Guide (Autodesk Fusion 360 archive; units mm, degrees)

design "Guide" references "Base"
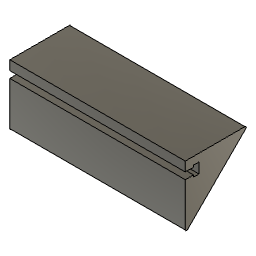
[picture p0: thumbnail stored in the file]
parameter "width" = 140
parameter "extra_padding" = 0
component_insert "Component Insert"
sketch "Sketch2" plane through (40, 0, 0) normal (1, 0, 0) x axis (0, 1, 0)
  line L1 (44.7318, 45.6759) -> (44.7318, 48.9559)
  line L2 (48.9918, 45.6759) -> (44.7318, 45.6759)
  line L3 (48.9918, 47.1259) -> (48.9918, 45.6759)
  line L4 (55.6118, 47.1259) -> (48.9918, 47.1259)
  line L5 (55.6118, 52.4859) -> (55.6118, 47.1259)
  line L6 (48.9918, 52.4859) -> (55.6118, 52.4859)
  line L7 (48.9918, 53.9359) -> (48.9918, 52.4859)
  line L8 (44.7318, 53.9359) -> (48.9918, 53.9359)
  line L9 (44.7318, 50.6559) -> (44.7318, 53.9359)
  line L10 (44.7318, 48.9559) -> (44.7318, 50.6559)
  line L11 (28.6118, 54.0559) -> (28.6118, 50.6559)
  line L12 (33.1118, 54.0559) -> (28.6118, 54.0559)
  line L13 (33.1118, 52.6059) -> (33.1118, 54.0559)
  line L14 (39.6118, 52.6059) -> (33.1118, 52.6059)
  line L15 (39.6118, 60) -> (39.6118, 52.6059)
  line L16 (19.6118, 60) -> (39.6118, 60)
  line L17 (19.6118, 23.2332) -> (19.6118, 60)
  line L18 (39.6118, 39.6118) -> (22.1725, 22.1725)
  line L19 (39.6118, 47.0059) -> (39.6118, 39.6118)
  line L20 (33.1118, 47.0059) -> (39.6118, 47.0059)
  line L21 (33.1118, 45.5559) -> (33.1118, 47.0059)
  line L22 (28.6118, 45.5559) -> (33.1118, 45.5559)
  line L23 (28.6118, 48.9559) -> (28.6118, 45.5559)
  arc A1 centre (44.7318, 49.8059) radius 0.85 clockwise from (44.7318, 50.6559) to (44.7318, 48.9559)
  arc A2 centre (44.7318, 49.8059) radius 0.85 clockwise from (44.7318, 50.6559) to (44.7318, 48.9559)
  arc A3 centre (28.6118, 49.8059) radius 0.85 clockwise from (28.6118, 48.9559) to (28.6118, 50.6559)
  arc A4 centre (21.1118, 23.2332) radius 1.5 clockwise from (22.1725, 22.1725) to (19.6118, 23.2332)
  point P14 (44.7318, 50.6559)
  point P16 (44.7318, 50.6559)
  point P2 (44.7318, 48.9559)
  point P17 (44.7318, 48.9559)
  coincident P14 P16
  coincident P2 P17
sketch "Sketch4" plane through (40, 50.1718, 49.8059) normal (1, 0, 0) x axis (0, 1, 0)
  line L1 (-5.44, -0.85) -> (-5.44, 0.85)
  line L2 (-5.44, 10.1941) -> (-5.44, 0)
  line L3 (-5.44, -39.8059) -> (-5.44, 10.1941)
  line L4 (75.5574, 41.1915) -> (-5.44, -39.8059)
  line L5 (109.1076, -39.8059) -> (-5.44, -39.8059)
  line L6 (86, 10.1941) -> (-5.44, 10.1941)
  point P5 (-5.44, 0)
  point P6 (-5.44, 10.1941)
  point P7 (-5.44, -39.8059)
  midpoint L1 P5
  horizontal L5
  perpendicular L2 L6
  dimension "d9" distance P6 P7 = 50
  dimension "d11" angle L4 L5 = 45
extrude "Extrude3" new body sketch "Sketch4" profile of L1 L3 L4 L6 along normal blind 140 (= "width")
extrude "Extrude4" cut sketch "Sketch2" profile of A1 L1 L2 L3 L4 L5 L6 L7 L8 L9 A2 L10 along normal blind 140 (= "width")
sketch "Filename" plane through (0, 0, 60) normal (0, 0, 1) x axis (1, 0, 0)
  dimension "d17" = 3
sketch "Fill wrong hole" plane through (180, 0, 0) normal (1, 0, 0) x axis (0, 1, 0)
  line L1 (48.9918, 53.9359) -> (44.7318, 53.9359)
  line L2 (48.9918, 52.4859) -> (48.9918, 53.9359)
  line L3 (55.6118, 52.4859) -> (48.9918, 52.4859)
  line L4 (55.6118, 47.1259) -> (55.6118, 52.4859)
  line L5 (48.9918, 47.1259) -> (55.6118, 47.1259)
  line L6 (48.9918, 45.6759) -> (48.9918, 47.1259)
  line L7 (44.7318, 45.6759) -> (48.9918, 45.6759)
  line L8 (44.7318, 10) -> (44.7318, 45.6759)
  line L9 (94.7318, 60) -> (44.7318, 10)
  line L10 (44.7318, 60) -> (94.7318, 60)
  line L11 (44.7318, 53.9359) -> (44.7318, 60)
  line L12 (44.7318, 45.6759) -> (44.7318, 53.9359)
  point P2 (44.7318, 53.9359)
  point P13 (44.7318, 53.9359)
  point P9 (44.7318, 45.6759)
  point P14 (44.7318, 45.6759)
  coincident P2 P13
  coincident P9 P14
extrude "Extrude5" add sketch "Fill wrong hole" profile of L1 L2 L3 L4 L5 L6 L7 L12 to an object
sketch "Sketch10" plane through (180, 0, 0) normal (1, 0, 0) x axis (0, 1, 0)
  line L1 (48.9918, 53.9359) -> (44.7318, 53.9359)
  line L2 (44.7318, 45.6759) -> (44.7318, 53.9359)
  line L3 (44.7318, 45.6759) -> (48.9918, 45.6759)
  line L4 (48.9918, 45.6759) -> (48.9918, 47.1259)
  line L5 (48.9918, 47.1259) -> (55.6118, 47.1259)
  line L6 (55.6118, 47.1259) -> (55.6118, 52.4859)
  line L7 (55.6118, 52.4859) -> (48.9918, 52.4859)
  line L8 (48.9918, 52.4859) -> (48.9918, 53.9359)
  line L9 (62.2318, 53.9359) -> (66.4918, 53.9359)
  line L10 (62.2318, 52.4859) -> (62.2318, 53.9359)
  line L11 (55.6118, 52.4859) -> (62.2318, 52.4859)
  line L12 (55.6118, 47.1259) -> (55.6118, 52.4859)
  line L13 (62.2318, 47.1259) -> (55.6118, 47.1259)
  line L14 (62.2318, 45.6759) -> (62.2318, 47.1259)
  line L15 (66.4918, 45.6759) -> (62.2318, 45.6759)
  line L16 (66.4918, 45.6759) -> (66.4918, 53.9359)
  point P2 (44.7318, 53.9359)
  point P12 (66.4918, 53.9359)
  point P3 (48.9918, 53.9359)
  point P13 (62.2318, 53.9359)
  point P4 (44.7318, 53.9359)
  point P20 (66.4918, 53.9359)
  point P5 (44.7318, 45.6759)
  point P21 (66.4918, 45.6759)
  point P6 (48.9918, 45.6759)
  point P18 (62.2318, 45.6759)
  point P7 (44.7318, 45.6759)
  point P19 (66.4918, 45.6759)
  point P8 (48.9918, 47.1259)
  point P17 (62.2318, 47.1259)
  point P9 (55.6118, 47.1259)
  point P16 (55.6118, 47.1259)
  point P10 (55.6118, 52.4859)
  point P15 (55.6118, 52.4859)
  point P11 (48.9918, 52.4859)
  point P14 (62.2318, 52.4859)
  symmetric P2 L6 P12
  symmetric P3 L6 P13
  symmetric P4 L6 P20
  symmetric P5 L6 P21
  symmetric P6 L6 P18
  symmetric P7 L6 P19
  symmetric P8 L6 P17
  symmetric P9 L6 P16
  symmetric P10 L6 P15
  symmetric L6 P11 P14
sketch "Sketch12" plane through (180, 0, 0) normal (1, 0, 0) x axis (0, 1, 0)
  line L1 (62.2318, 53.9359) -> (66.4918, 53.9359)
  line L2 (62.2318, 52.4859) -> (62.2318, 53.9359)
  line L3 (55.6118, 47.1259) -> (55.6118, 52.4859)
  line L4 (62.2318, 47.1259) -> (55.6118, 47.1259)
  line L5 (62.2318, 45.6759) -> (62.2318, 47.1259)
  line L6 (66.4918, 45.6759) -> (62.2318, 45.6759)
  line L7 (55.6118, 52.4859) -> (62.2318, 52.4859)
  line L8 (66.4918, 45.6759) -> (66.4918, 53.9359)
  line L9 (51.3518, 53.9359) -> (55.6118, 53.9359)
  line L10 (51.3518, 52.4859) -> (51.3518, 53.9359)
  line L11 (44.7318, 52.4859) -> (51.3518, 52.4859)
  line L12 (44.7318, 47.1259) -> (44.7318, 52.4859)
  line L13 (51.3518, 47.1259) -> (44.7318, 47.1259)
  line L14 (51.3518, 45.6759) -> (51.3518, 47.1259)
  line L15 (55.6118, 45.6759) -> (51.3518, 45.6759)
  line L16 (55.6118, 45.6759) -> (55.6118, 53.9359)
  dimension "d22" R-Pattern1-uDistance = -10.88
  dimension "d23" R-Pattern1-vDistance = 0
extrude "Extrude6" cut sketch "Sketch12" profile of L3 L9 L10 L11 L12 L13 L14 L15 L16 to an object
extrude "Extrude8" add of existing geometry blind 0 (= "extra_padding")
sketch "Sketch13" plane through (0, 0, 61) normal (0, 0, 1) x axis (-1, 0, 0)
  dimension "d33" = 3
sketch "Sketch15" plane through (0, 17.3659, -17.3659) normal (0, 0.7071, -0.7071) x axis (-1, 0, 0)
  dimension "d36" = 3
extrude "Extrude10" cut sketch "Sketch15" against normal blind 2
fillet "Fillet1" radius 1
extrude "Extrude9" cut sketch "Sketch13" against normal blind 2
sketch "Sketch14" plane through (0, 0, 60) normal (0, 0, 1) x axis (-1, 0, 0)
  line L1 (-40, -92.3176) -> (-180, -92.3176)
  line L2 (-40, -44.7318) -> (-40, -92.3176)
  line L3 (-180, -44.7318) -> (-40, -44.7318)
  line L4 (-180, -92.3176) -> (-180, -44.7318)

design "Base"
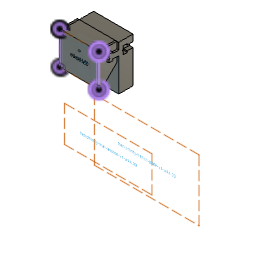
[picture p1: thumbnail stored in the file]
parameter "wall_anchor_height" = 60
parameter "wall_anchor_width" = 20
parameter "wall_anchor_angle" = 45
parameter "width_per_slot" = 40
parameter "slot_inner_width" = 8.5
parameter "slot_inner_height" = 4.5
parameter "slot_outer_width" = 5.6
parameter "slot_outer_height" = 6.5
parameter "slot_dept" = 15
parameter "print_tolerance" = 0.12
parameter "base_plate_thickness" = 16
parameter "base_plate_slot_height" = 50
parameter "wall_anchor_angle_rounded_border" = 1.5
parameter "base_plate_screw_hole_diameter" = 4
parameter "base_plate_screw_head_diameter" = 8
parameter "base_plate_screw_head_height" = 4
parameter "base_plate_screw_hole_side_distance" = 7
parameter "slot_screw_head_width" = 4.42 (= "4.3 mm + print_tolerance")
parameter "slot_screw_thread_width" = 2.12 (= "2 mm + print_tolerance")
parameter "slot_screw_head_height" = 2.12 (= "2 mm + print_tolerance")
parameter "width" = 44
parameter "filament_hole_width" = 1.7
sketch "Side" plane through (0, 0, 0) normal (1, 0, 0) x axis (0, 1, 0)
  line L1 (39.6118, 0) -> (19.6118, 0)
  line L2 (39.6118, 60) -> (39.6118, 0)
  line L3 (19.6118, 60) -> (39.6118, 60)
  line L4 (19.6118, 0) -> (19.6118, 60)
  line L5 (39.6118, 39.6118) -> (0, 0)
  line L6 (56.0196, 0) -> (0, 0)
  point P1 (0, 0)
  point P6 (0, 0)
  point P7 (39.6118, 39.6118)
  point P2 (19.6118, 0)
  point P3 (39.6118, 0)
  point P5 (19.6118, 60)
  horizontal L1
  vertical L2
  horizontal L3
  vertical L4
  horizontal L6
  coincident P1 P6
  coincident L2 P7
  dimension "d4" distance P2 P3 = 20 (= "wall_anchor_width")
  dimension "d5" distance P2 P5 = 60 (= "wall_anchor_height")
  dimension "d6" angle L5 L6 = 45 (= "wall_anchor_angle")
extrude "Extrude1" new body sketch "Side" profile of L1 L2 L3 L4 L5 along normal blind 40 (= "width_per_slot")
sketch "Slot LeftToRight" plane through (0, 0, 0) normal (-1, 0, 0) x axis (0, -1, 0)
  line L1 (-19.6118, 60) -> (-19.6118, 19.6118)
  line L2 (-39.6118, 60) -> (-19.6118, 60)
  line L3 (-39.6118, 39.6118) -> (-39.6118, 60)
  line L4 (-19.6118, 19.6118) -> (-39.6118, 39.6118)
  line L5 (-39.6118, 52.6059) -> (-39.6118, 49.8059)
  line L6 (-39.6118, 47.0059) -> (-39.6118, 49.8059)
  line L7 (-33.1118, 52.6059) -> (-39.6118, 52.6059)
  line L8 (-28.6118, 49.8059) -> (-39.6118, 49.8059)
  line L9 (-28.6118, 54.0559) -> (-28.6118, 49.8059)
  line L10 (-33.1118, 54.0559) -> (-28.6118, 54.0559)
  line L11 (-33.1118, 52.6059) -> (-33.1118, 54.0559)
  line L12 (-28.6118, 45.5559) -> (-28.6118, 49.8059)
  line L13 (-33.1118, 45.5559) -> (-28.6118, 45.5559)
  line L14 (-33.1118, 47.0059) -> (-33.1118, 45.5559)
  line L15 (-33.1118, 47.0059) -> (-39.6118, 47.0059)
  point P6 (-39.6118, 49.8059)
  point P7 (-39.6118, 52.6059)
  point P17 (-39.6118, 47.0059)
  point P9 (-33.1118, 52.6059)
  point P16 (-33.1118, 47.0059)
  point P10 (-28.6118, 49.8059)
  point P13 (-28.6118, 49.8059)
  point P11 (-28.6118, 54.0559)
  point P14 (-28.6118, 45.5559)
  point P12 (-33.1118, 54.0559)
  point P15 (-33.1118, 45.5559)
  midpoint L3 P6
  parallel L3 L5
  parallel L3 L6
  perpendicular L3 L7
  perpendicular L6 L8
  perpendicular L8 L9
  perpendicular L9 L10
  symmetric P7 L8 P17
  symmetric P9 L8 P16
  symmetric P10 L8 P13
  symmetric L8 P11 P14
  symmetric L8 P12 P15
  dimension "d80" distance P6 P7 = 2.8 (= "slot_outer_width / 2")
  dimension "d82" distance P7 P9 = 6.5 (= "slot_outer_height")
  dimension "d84" distance P6 P10 = 11 (= "slot_outer_height + slot_inner_height")
  dimension "d85" distance P10 P11 = 4.25 (= "slot_inner_width / 2")
  dimension "d86" distance P11 P12 = 4.5 (= "slot_inner_height")
extrude "Extrude3" cut sketch "Slot LeftToRight" profile of L3 L5 L6 L7 L9 L10 L11 L12 L13 L14 L15 against normal blind 40 (magnitude of "width_per_slot * -1")
sketch "Plate" plane through (0, 39.6118, 0) normal (0, 1, 0) x axis (-1, 0, 0)
  line L1 (0, 39.6118) -> (-40, 39.6118)
  line L2 (-40, 60) -> (0, 60)
  line L3 (0, 10) -> (0, 60)
  line L4 (-40, 10) -> (-40, 60)
  line L5 (-40, 10) -> (0, 10)
  line L6 (-40, 47.0059) -> (0, 47.0059)
  line L7 (-40, 52.6059) -> (-40, 60)
  line L8 (0, 60) -> (0, 52.6059)
  line L9 (0, 52.6059) -> (-40, 52.6059)
  line L10 (-40, 60) -> (0, 60)
  line L11 (-40, 39.6118) -> (-40, 47.0059)
  line L12 (0, 47.0059) -> (0, 39.6118)
  point P2 (0, 60)
  point P3 (-40, 60)
  point P4 (0, 10)
  point P5 (-40, 10)
  perpendicular L1 L3
  perpendicular L1 L4
  dimension "d36" distance P2 P3 = 40 (= "width_per_slot")
  dimension "d37" distance P2 P4 = 50 (= "base_plate_slot_height")
  dimension "d39" distance P3 P5 = 50 (= "base_plate_slot_height")
extrude "Extrude6" new body sketch "Plate" profile of L1 L2 L3 L4 L5 L6 L7 L8 L9 L10 along normal blind 16 (= "base_plate_thickness") bodies "Base plate with slot"
sketch "Slot" plane through (0, 0, 0) normal (-1, 0, 0) x axis (0, -1, 0)
  line L1 (-19.6118, 60) -> (-19.6118, 19.6118)
  line L2 (-39.6118, 60) -> (-19.6118, 60)
  line L3 (-39.6118, 52.6059) -> (-39.6118, 60)
  line L4 (-33.1118, 52.6059) -> (-39.6118, 52.6059)
  line L5 (-33.1118, 54.0559) -> (-33.1118, 52.6059)
  line L6 (-28.6118, 54.0559) -> (-33.1118, 54.0559)
  line L7 (-28.6118, 45.5559) -> (-28.6118, 54.0559)
  line L8 (-33.1118, 45.5559) -> (-28.6118, 45.5559)
  line L9 (-33.1118, 47.0059) -> (-33.1118, 45.5559)
  line L10 (-39.6118, 47.0059) -> (-33.1118, 47.0059)
  line L11 (-39.6118, 39.6118) -> (-39.6118, 47.0059)
  line L12 (-19.6118, 19.6118) -> (-39.6118, 39.6118)
  line L13 (-33.1118, 52.6059) -> (-39.6118, 52.6059)
  line L14 (-33.1118, 54.0559) -> (-33.1118, 52.6059)
  line L15 (-28.6118, 54.0559) -> (-33.1118, 54.0559)
  line L16 (-28.6118, 45.5559) -> (-28.6118, 54.0559)
  line L17 (-33.1118, 45.5559) -> (-28.6118, 45.5559)
  line L18 (-33.1118, 47.0059) -> (-33.1118, 45.5559)
  line L19 (-39.6118, 47.0059) -> (-33.1118, 47.0059)
  line L20 (-39.6118, 10) -> (-39.6118, 60)
  line L21 (-32.9918, 52.4859) -> (-39.6118, 52.4859)
  line L22 (-32.9918, 53.9359) -> (-32.9918, 52.4859)
  line L23 (-28.7318, 53.9359) -> (-32.9918, 53.9359)
  line L24 (-28.7318, 45.6759) -> (-28.7318, 53.9359)
  line L25 (-32.9918, 45.6759) -> (-28.7318, 45.6759)
  line L26 (-32.9918, 47.1259) -> (-32.9918, 45.6759)
  line L27 (-39.6118, 47.1259) -> (-32.9918, 47.1259)
  line L28 (-33.1118, 52.6059) -> (-39.6118, 52.6059)
  line L29 (-33.1118, 52.6059) -> (-33.1118, 54.0559)
  line L30 (-28.6118, 54.0559) -> (-33.1118, 54.0559)
  line L31 (-28.6118, 45.5559) -> (-28.6118, 54.0559)
  line L32 (-33.1118, 45.5559) -> (-28.6118, 45.5559)
  line L33 (-33.1118, 47.0059) -> (-33.1118, 45.5559)
  line L34 (-39.6118, 47.0059) -> (-33.1118, 47.0059)
  line L35 (-39.6118, 47.0059) -> (-39.6118, 52.6059)
  line L36 (-49.1118, 52.6059) -> (-55.6118, 52.6059)
  line L37 (-49.1118, 52.6059) -> (-49.1118, 54.0559)
  line L38 (-44.6118, 54.0559) -> (-49.1118, 54.0559)
  line L39 (-44.6118, 45.5559) -> (-44.6118, 54.0559)
  line L40 (-49.1118, 45.5559) -> (-44.6118, 45.5559)
  line L41 (-49.1118, 47.0059) -> (-49.1118, 45.5559)
  line L42 (-55.6118, 47.0059) -> (-49.1118, 47.0059)
  line L43 (-55.6118, 47.0059) -> (-55.6118, 52.6059)
  point P15 (-39.6118, 52.6059)
  point P33 (-39.6118, 52.6059)
  point P16 (-33.1118, 52.6059)
  point P34 (-33.1118, 52.6059)
  point P17 (-33.1118, 54.0559)
  point P35 (-33.1118, 54.0559)
  point P36 (-33.1118, 52.6059)
  point P18 (-28.6118, 54.0559)
  point P37 (-28.6118, 54.0559)
  point P19 (-28.6118, 45.5559)
  point P38 (-28.6118, 45.5559)
  point P10 (-28.6118, 45.5559)
  point P39 (-28.6118, 45.5559)
  point P11 (-33.1118, 45.5559)
  point P40 (-33.1118, 45.5559)
  point P41 (-33.1118, 45.5559)
  point P12 (-33.1118, 47.0059)
  point P42 (-33.1118, 47.0059)
  point P21 (-33.1118, 47.0059)
  point P43 (-33.1118, 47.0059)
  point P22 (-39.6118, 47.0059)
  point P44 (-39.6118, 47.0059)
  point P45 (-39.6118, 52.6059)
  point P46 (-39.6118, 47.0059)
  coincident P15 P33
  coincident P16 P34
  coincident P17 P35
  coincident P16 P36
  coincident P18 P37
  coincident P19 P38
  coincident P10 P39
  coincident P11 P40
  coincident P11 P41
  coincident P12 P42
  coincident P21 P43
  coincident P22 P44
  coincident P15 P45
  coincident P22 P46
  dimension "d91" = 0.12 (= "print_tolerance")
  dimension "d96" R-Pattern1-uDistance = -16 (= "base_plate_thickness * -1")
  dimension "d97" R-Pattern1-vDistance = 0
extrude "Extrude7" add sketch "Slot" profile of L20 L24 L23 L27 L22 L25 L26 L21 against normal blind 40 (magnitude of "width_per_slot * -1")
extrude "Extrude8" cut sketch "Slot" profile of L36 L37 L38 L39 L40 L41 L42 L43 no distance stored
sketch "Sketch3" plane through (0, 0, 0) normal (-1, 0, 0) x axis (0, -1, 0)
  line L1 (-32.9918, 47.1259) -> (-39.6118, 47.1259)
  line L2 (-32.9918, 45.6759) -> (-32.9918, 47.1259)
  line L3 (-28.7318, 45.6759) -> (-32.9918, 45.6759)
  line L4 (-28.7318, 53.9359) -> (-28.7318, 45.6759)
  line L5 (-32.9918, 53.9359) -> (-28.7318, 53.9359)
  line L6 (-32.9918, 52.4859) -> (-32.9918, 53.9359)
  line L7 (-39.6118, 52.4859) -> (-32.9918, 52.4859)
  line L8 (-44.6118, 45.5559) -> (-44.6118, 54.0559)
  line L9 (-32.9918, 52.4859) -> (-39.6118, 52.4859)
  line L10 (-32.9918, 53.9359) -> (-32.9918, 52.4859)
  line L11 (-28.7318, 53.9359) -> (-32.9918, 53.9359)
  line L12 (-28.7318, 45.6759) -> (-28.7318, 53.9359)
  line L13 (-32.9918, 45.6759) -> (-28.7318, 45.6759)
  line L14 (-32.9918, 47.1259) -> (-32.9918, 45.6759)
  line L15 (-39.6118, 47.1259) -> (-32.9918, 47.1259)
  line L16 (-39.6118, 47.1259) -> (-39.6118, 52.4859)
  line L17 (-55.6118, 52.4859) -> (-48.9918, 52.4859)
  line L18 (-48.9918, 52.4859) -> (-48.9918, 53.9359)
  line L19 (-48.9918, 53.9359) -> (-44.7318, 53.9359)
  line L20 (-44.7318, 45.6759) -> (-44.7318, 53.9359)
  line L21 (-48.9918, 45.6759) -> (-44.7318, 45.6759)
  line L22 (-48.9918, 47.1259) -> (-48.9918, 45.6759)
  line L23 (-55.6118, 47.1259) -> (-48.9918, 47.1259)
  line L24 (-55.6118, 47.1259) -> (-55.6118, 52.4859)
  line L25 (-55.6118, 47.0059) -> (-49.1118, 47.0059)
  line L26 (-55.6118, 10) -> (-55.6118, 47.0059)
  line L27 (-39.6118, 10) -> (-55.6118, 10)
  line L28 (-39.6118, 47.1259) -> (-39.6118, 10)
  line L29 (-39.6118, 60) -> (-39.6118, 52.4859)
  line L30 (-55.6118, 60) -> (-39.6118, 60)
  line L31 (-55.6118, 52.6059) -> (-55.6118, 60)
  line L32 (-49.1118, 52.6059) -> (-55.6118, 52.6059)
  line L33 (-49.1118, 54.0559) -> (-49.1118, 52.6059)
  line L34 (-44.6118, 54.0559) -> (-49.1118, 54.0559)
  line L35 (-49.1118, 45.5559) -> (-44.6118, 45.5559)
  line L36 (-49.1118, 47.0059) -> (-49.1118, 45.5559)
  point P9 (-39.6118, 52.4859)
  point P20 (-39.6118, 52.4859)
  point P19 (-39.6118, 47.1259)
  point P21 (-39.6118, 47.1259)
  coincident P9 P20
  coincident P19 P21
  dimension "d105" R-Pattern1-vDistance = 0
extrude "Extrude3" new body sketch "Sketch3" profile of L17 L18 L19 L20 L21 L22 L23 L24 against normal blind 40 (magnitude of "width_per_slot * -1")
sketch "Screw hole" plane through (0, 28.6118, 0) normal (0, 1, 0) x axis (-1, 0, 0)
  line L1 (0, 54.0559) -> (0, 45.5559)
  line L2 (-40, 54.0559) -> (0, 54.0559)
  line L3 (-40, 45.5559) -> (-40, 54.0559)
  line L4 (0, 45.5559) -> (-40, 45.5559)
  line L5 (0, 45.5559) -> (-40, 54.0559)
  line L6 (-40, 45.5559) -> (0, 54.0559)
  circle C1 centre (-20, 49.8059) radius 2.21
  circle C2 centre (-20, 49.8059) radius 1.06
  point P4 (-40, 54.0559)
  point P6 (-40, 54.0559)
  point P2 (0, 45.5559)
  point P7 (0, 45.5559)
  point P3 (0, 54.0559)
  point P8 (0, 54.0559)
  point P5 (-40, 45.5559)
  point P9 (-40, 45.5559)
  point P10 (-20, 49.8059)
  coincident P4 P6
  coincident P2 P7
  coincident P3 P8
  coincident P5 P9
  midpoint L5 P10
  concentric C1 C2
  dimension "d119" diameter C1 = 4.42 (= "slot_screw_head_width")
  dimension "d120" diameter C2 = 2.12 (= "slot_screw_thread_width")
extrude "Extrude4" cut sketch "Screw hole" profile of C2 against normal blind 2000
extrude "Extrude5" cut sketch "Screw hole" profile of C1 C2 no distance stored
fillet "Fillet1" radius 1.5 (= "wall_anchor_angle_rounded_border")
work_plane "WorkPlane1" sketch "Slot LeftToRight" AlongDistance -20 (= "-width_per_slot / 2")
sketch "Screw head" plane through (20, 0, 0) normal (-1, 0, 0) x axis (0, -1, 0)
  line L1 (-28.6118, 52.0159) -> (-28.6118, 47.5959)
  line L2 (-26.4918, 52.0159) -> (-26.4918, 47.5959)
  line L3 (-26.4918, 48.7459) -> (-26.4918, 50.8659)
  line L4 (-26.4918, 50.8659) -> (-28.6118, 52.0159)
  line L5 (-26.4918, 52.0159) -> (-28.6118, 52.0159)
  point P3 (-28.6118, 52.0159)
  point P8 (-28.6118, 52.0159)
  point P6 (-26.4918, 50.8659)
  point P9 (-26.4918, 50.8659)
  point P10 (-28.6118, 52.0159)
  point P5 (-26.4918, 52.0159)
  point P11 (-26.4918, 52.0159)
  coincident P3 P8
  coincident P6 P9
  coincident P3 P10
  coincident P5 P11
revolve "Revolve1" sketch "Screw head" AlongAngle 360
sketch "Plate" plane through (0, 39.6118, 0) normal (0, 1, 0) x axis (-1, 0, 0)
  line L1 (0, 39.6118) -> (-40, 39.6118)
  line L2 (-40, 60) -> (0, 60)
  line L3 (0, 10) -> (0, 60)
  line L4 (-40, 10) -> (-40, 60)
  line L5 (-40, 10) -> (0, 10)
  line L6 (-40, 47.0059) -> (0, 47.0059)
  line L7 (-40, 39.6118) -> (-40, 47.0059)
  line L8 (0, 47.0059) -> (0, 39.6118)
  line L9 (0, 52.6059) -> (-40, 52.6059)
  line L10 (-40, 60) -> (0, 60)
  line L11 (0, 60) -> (0, 52.6059)
  line L12 (-40, 52.6059) -> (-40, 60)
  point P2 (0, 60)
  point P3 (-40, 60)
  point P4 (0, 10)
  point P5 (-40, 10)
  perpendicular L1 L3
  perpendicular L1 L4
  dimension "d36_1" distance P2 P3 = 40 (= "width_per_slot")
  dimension "d37_1" distance P2 P4 = 50 (= "base_plate_slot_height")
  dimension "d39_1" distance P3 P5 = 50 (= "base_plate_slot_height")
extrude "Extrude6" new body sketch "Plate" profile of L1 L2 L3 L4 L5 L6 L7 L8 L9 L10 along normal blind 16 (= "base_plate_thickness") named "d89_1" bodies "Base plate with slot"
sketch "Slot" plane through (0, 0, 0) normal (-1, 0, 0) x axis (0, -1, 0)
  line L1 (-19.6118, 60) -> (-19.6118, 23.2332)
  line L2 (-39.6118, 60) -> (-19.6118, 60)
  line L3 (-39.6118, 52.6059) -> (-39.6118, 60)
  line L4 (-33.1118, 52.6059) -> (-39.6118, 52.6059)
  line L5 (-33.1118, 54.0559) -> (-33.1118, 52.6059)
  line L6 (-28.6118, 54.0559) -> (-33.1118, 54.0559)
  line L7 (-28.6118, 45.5559) -> (-28.6118, 54.0559)
  line L8 (-33.1118, 45.5559) -> (-28.6118, 45.5559)
  line L9 (-33.1118, 47.0059) -> (-33.1118, 45.5559)
  line L10 (-39.6118, 47.0059) -> (-33.1118, 47.0059)
  line L11 (-39.6118, 39.6118) -> (-39.6118, 47.0059)
  line L12 (-22.1725, 22.1725) -> (-39.6118, 39.6118)
  line L13 (-33.1118, 52.6059) -> (-39.6118, 52.6059)
  line L14 (-33.1118, 54.0559) -> (-33.1118, 52.6059)
  line L15 (-28.6118, 54.0559) -> (-33.1118, 54.0559)
  line L16 (-28.6118, 45.5559) -> (-28.6118, 54.0559)
  line L17 (-33.1118, 45.5559) -> (-28.6118, 45.5559)
  line L18 (-33.1118, 47.0059) -> (-33.1118, 45.5559)
  line L19 (-39.6118, 47.0059) -> (-33.1118, 47.0059)
  line L20 (-39.6118, 10) -> (-39.6118, 60)
  line L21 (-32.9918, 52.4859) -> (-39.6118, 52.4859)
  line L22 (-32.9918, 53.9359) -> (-32.9918, 52.4859)
  line L23 (-28.7318, 53.9359) -> (-32.9918, 53.9359)
  line L24 (-28.7318, 45.6759) -> (-28.7318, 53.9359)
  line L25 (-32.9918, 45.6759) -> (-28.7318, 45.6759)
  line L26 (-32.9918, 47.1259) -> (-32.9918, 45.6759)
  line L27 (-39.6118, 47.1259) -> (-32.9918, 47.1259)
  line L28 (-33.1118, 52.6059) -> (-39.6118, 52.6059)
  line L29 (-33.1118, 52.6059) -> (-33.1118, 54.0559)
  line L30 (-28.6118, 54.0559) -> (-33.1118, 54.0559)
  line L31 (-28.6118, 45.5559) -> (-28.6118, 54.0559)
  line L32 (-33.1118, 45.5559) -> (-28.6118, 45.5559)
  line L33 (-33.1118, 47.0059) -> (-33.1118, 45.5559)
  line L34 (-39.6118, 47.0059) -> (-33.1118, 47.0059)
  line L35 (-39.6118, 47.0059) -> (-39.6118, 52.6059)
  line L36 (-49.1118, 52.6059) -> (-55.6118, 52.6059)
  line L37 (-49.1118, 52.6059) -> (-49.1118, 54.0559)
  line L38 (-44.6118, 54.0559) -> (-49.1118, 54.0559)
  line L39 (-44.6118, 45.5559) -> (-44.6118, 54.0559)
  line L40 (-49.1118, 45.5559) -> (-44.6118, 45.5559)
  line L41 (-49.1118, 47.0059) -> (-49.1118, 45.5559)
  line L42 (-55.6118, 47.0059) -> (-49.1118, 47.0059)
  line L43 (-55.6118, 47.0059) -> (-55.6118, 52.6059)
  arc A1 centre (-21.1118, 23.2332) radius 1.5 clockwise from (-19.6118, 23.2332) to (-22.1725, 22.1725)
  point P15 (-39.6118, 52.6059)
  point P33 (-39.6118, 52.6059)
  point P16 (-33.1118, 52.6059)
  point P34 (-33.1118, 52.6059)
  point P17 (-33.1118, 54.0559)
  point P35 (-33.1118, 54.0559)
  point P36 (-33.1118, 52.6059)
  point P18 (-28.6118, 54.0559)
  point P37 (-28.6118, 54.0559)
  point P19 (-28.6118, 45.5559)
  point P38 (-28.6118, 45.5559)
  point P10 (-28.6118, 45.5559)
  point P39 (-28.6118, 45.5559)
  point P11 (-33.1118, 45.5559)
  point P40 (-33.1118, 45.5559)
  point P41 (-33.1118, 45.5559)
  point P12 (-33.1118, 47.0059)
  point P42 (-33.1118, 47.0059)
  point P21 (-33.1118, 47.0059)
  point P43 (-33.1118, 47.0059)
  point P22 (-39.6118, 47.0059)
  point P44 (-39.6118, 47.0059)
  point P45 (-39.6118, 52.6059)
  point P46 (-39.6118, 47.0059)
  coincident P15 P33
  coincident P16 P34
  coincident P17 P35
  coincident P16 P36
  coincident P18 P37
  coincident P19 P38
  coincident P10 P39
  coincident P11 P40
  coincident P11 P41
  coincident P12 P42
  coincident P21 P43
  coincident P22 P44
  coincident P15 P45
  coincident P22 P46
  dimension "d91_1" = 0.12 (= "print_tolerance")
  dimension "d96_1" R-Pattern1-uDistance = -16 (= "base_plate_thickness * -1")
  dimension "d97_1" R-Pattern1-vDistance = 0
extrude "Extrude8" cut sketch "Slot" profile of L36 L37 L38 L39 L40 L41 L42 L43 no distance stored
sketch "Screw" plane through (0, 55.6118, 0) normal (0, 1, 0) x axis (-1, 0, 0)
  line L1 (-40, 47.0059) -> (0, 47.0059)
  line L2 (-40, 10) -> (-40, 47.0059)
  line L3 (0, 10) -> (-40, 10)
  line L4 (0, 47.0059) -> (0, 10)
  line L5 (-33, 17) -> (-33, 40.0059)
  line L6 (-7, 17) -> (-33, 17)
  line L7 (-7, 40.0059) -> (-7, 17)
  line L8 (-33, 40.0059) -> (-7, 40.0059)
  circle C1 centre (-33, 17) radius 4
  circle C2 centre (-33, 17) radius 2
  point P7 (-33, 17)
  point P10 (-33, 17)
  coincident P7 P10
  concentric C1 C2
  dimension "d127" = -7 (= "base_plate_screw_hole_side_distance * -1")
  dimension "d128" diameter C1 = 8
  dimension "d129" diameter C2 = 4
rectangular_pattern "R-Pattern2" countU 1 (= "floor(( width / mm ) / ( width_per_slot / cm * 10 ))") uSpaceDistance 40 (= "width_per_slot") vSpaceDistance 0
work_plane "WorkPlane2"
extrude "Extrude12" new body of existing geometry no distance stored
mirror "Mirror3" mirrorStitchTolerance 0.1
sketch "filename" plane through (0, 19.6118, 0) normal (0, -1, 0) x axis (1, 0, 0)
  dimension "d216" = 3
sketch "Sketch14" plane through (0, 19.6118, 0) normal (0, -1, 0) x axis (1, 0, 0)
  line L1 (42, 60) -> (42, 23.2332)
  line L2 (40, 23.2332) -> (40, 60)
  line L3 (42, 23.2332) -> (40, 23.2332)
  line L4 (42, 60) -> (42, 23.2332)
  line L5 (40, 60) -> (42, 60)
  line L6 (0, 60) -> (0, 23.2332)
  line L7 (-2, 60) -> (0, 60)
  line L8 (-2, 23.2332) -> (-2, 60)
  line L9 (0, 23.2332) -> (-2, 23.2332)
  curve K1
  curve K2
  curve K3
  curve K4
  point P4 (42, 23.2332)
  point P2 (-2, 60)
  coincident P4
  coincident P2
  dimension "d229" Text1-Height = 3
extrude "Extrude19" cut sketch "Sketch14" against normal blind 2
extrude "Extrude14" cut of existing geometry blind 2 (= "( width_per_slot - width ) / -2")
extrude "Extrude15" cut of existing geometry blind 2 (= "( width_per_slot - width ) / -2")
extrude "Extrude9" cut of existing geometry blind -39 (= "-width_per_slot + 1 mm")
extrude "Extrude10" add of existing geometry blind 43 (= "width - 1 mm")
sketch "Sketch7" plane through (0, 39.6118, 0) normal (0, -1, 0) x axis (1, 0, 0)
  dimension "d236" = 3
extrude "Extrude11" cut sketch "Sketch7" against normal blind 2
sketch "Sketch8" plane through (0, 39.6118, 0) normal (0, -1, 0) x axis (1, 0, 0)
  line L1 (16.0624, 30.0752) -> (15.825, 30.0752)
  line L2 (16.0624, 27.063) -> (16.0624, 30.0752)
  line L3 (15.6941, 27.063) -> (16.0624, 27.063)
  line L4 (15.6941, 29.4102) -> (15.6941, 27.063)
  curve K1 (15.3441, 29.1564) -> (15.6941, 29.4102)
  curve K2 (14.9574, 28.9661) -> (15.3441, 29.1564)
  line L5 (14.9574, 29.3222) -> (14.9574, 28.9661)
  curve K3 (15.4976, 29.6741) -> (14.9574, 29.3222)
  curve K4 (15.825, 30.0752) -> (15.4976, 29.6741)
  line L6 (19.2896, 27.063) -> (19.7295, 28.7349)
  line L7 (18.9048, 27.063) -> (19.2896, 27.063)
  line L8 (18.2398, 29.2362) -> (18.9048, 27.063)
  line L9 (18.6204, 29.2362) -> (18.2398, 29.2362)
  line L10 (18.9662, 27.9818) -> (18.6204, 29.2362)
  line L11 (19.0952, 27.5152) -> (18.9662, 27.9818)
  curve K5 (19.2077, 27.9634) -> (19.0952, 27.5152)
  line L12 (19.5535, 29.2362) -> (19.2077, 27.9634)
  line L13 (19.9321, 29.2362) -> (19.5535, 29.2362)
  line L14 (20.2575, 27.9756) -> (19.9321, 29.2362)
  line L15 (20.366, 27.5602) -> (20.2575, 27.9756)
  line L16 (20.4908, 27.9797) -> (20.366, 27.5602)
  line L17 (20.8632, 29.2362) -> (20.4908, 27.9797)
  line L18 (21.2213, 29.2362) -> (20.8632, 29.2362)
  line L19 (20.5419, 27.063) -> (21.2213, 29.2362)
  line L20 (20.1593, 27.063) -> (20.5419, 27.063)
  line L21 (19.8134, 28.3645) -> (20.1593, 27.063)
  line L22 (19.7295, 28.7349) -> (19.8134, 28.3645)
  line L23 (22.9771, 27.063) -> (22.9771, 27.7812)
  line L24 (22.6088, 27.063) -> (22.9771, 27.063)
  line L25 (22.6088, 27.7812) -> (22.6088, 27.063)
  line L26 (21.3073, 27.7812) -> (22.6088, 27.7812)
  line L27 (21.3073, 28.1189) -> (21.3073, 27.7812)
  line L28 (22.6763, 30.063) -> (21.3073, 28.1189)
  line L29 (22.9771, 30.063) -> (22.6763, 30.063)
  line L30 (22.9771, 28.1189) -> (22.9771, 30.063)
  line L31 (23.3823, 28.1189) -> (22.9771, 28.1189)
  line L32 (23.3823, 27.7812) -> (23.3823, 28.1189)
  line L33 (22.9771, 27.7812) -> (23.3823, 27.7812)
  line L34 (26.7159, 27.063) -> (26.7159, 27.4825)
  line L35 (26.2964, 27.063) -> (26.7159, 27.063)
  line L36 (26.2964, 27.4825) -> (26.2964, 27.063)
  line L37 (26.7159, 27.4825) -> (26.2964, 27.4825)
  curve K6 (27.5508, 27.3228) -> (28.2323, 27.0118)
  curve K7 (27.2541, 28.5425) -> (27.5508, 27.3228)
  curve K8 (27.3626, 29.3979) -> (27.2541, 28.5425)
  curve K9 (27.6879, 29.8992) -> (27.3626, 29.3979)
  curve K10 (28.2323, 30.0752) -> (27.6879, 29.8992)
  curve K11 (28.6559, 29.977) -> (28.2323, 30.0752)
  curve K12 (28.9567, 29.6967) -> (28.6559, 29.977)
  curve K13 (29.1429, 29.2505) -> (28.9567, 29.6967)
  curve K14 (29.2104, 28.5425) -> (29.1429, 29.2505)
  curve K15 (29.102, 27.6892) -> (29.2104, 28.5425)
  curve K16 (28.7766, 27.1878) -> (29.102, 27.6892)
  curve K17 (28.2323, 27.0118) -> (28.7766, 27.1878)
  line L38 (25.308, 27.063) -> (25.308, 27.7812)
  line L39 (24.9396, 27.063) -> (25.308, 27.063)
  line L40 (24.9396, 27.7812) -> (24.9396, 27.063)
  line L41 (23.6381, 27.7812) -> (24.9396, 27.7812)
  line L42 (23.6381, 28.1189) -> (23.6381, 27.7812)
  line L43 (25.0072, 30.063) -> (23.6381, 28.1189)
  line L44 (25.308, 30.063) -> (25.0072, 30.063)
  line L45 (25.308, 28.1189) -> (25.308, 30.063)
  line L46 (25.7132, 28.1189) -> (25.308, 28.1189)
  line L47 (25.7132, 27.7812) -> (25.7132, 28.1189)
  line L48 (25.308, 27.7812) -> (25.7132, 27.7812)
  curve K18 (29.8816, 27.3228) -> (30.5631, 27.0118)
  curve K19 (29.5849, 28.5425) -> (29.8816, 27.3228)
  curve K20 (29.6934, 29.3979) -> (29.5849, 28.5425)
  curve K21 (30.0188, 29.8992) -> (29.6934, 29.3979)
  curve K22 (30.5631, 30.0752) -> (30.0188, 29.8992)
  curve K23 (30.9867, 29.977) -> (30.5631, 30.0752)
  curve K24 (31.2875, 29.6967) -> (30.9867, 29.977)
  curve K25 (31.4737, 29.2505) -> (31.2875, 29.6967)
  curve K26 (31.5413, 28.5425) -> (31.4737, 29.2505)
  curve K27 (31.4328, 27.6892) -> (31.5413, 28.5425)
  curve K28 (31.1074, 27.1878) -> (31.4328, 27.6892)
  curve K29 (30.5631, 27.0118) -> (31.1074, 27.1878)
  line L49 (18.0965, 27.9634) -> (18.0965, 28.3338)
  line L50 (16.9649, 27.9634) -> (18.0965, 27.9634)
  line L51 (16.9649, 28.3338) -> (16.9649, 27.9634)
  line L52 (18.0965, 28.3338) -> (16.9649, 28.3338)
  line L53 (13.6293, 27.063) -> (14.4519, 29.2362)
  line L54 (13.2855, 27.063) -> (13.6293, 27.063)
  line L55 (12.4587, 29.2362) -> (13.2855, 27.063)
  line L56 (12.8475, 29.2362) -> (12.4587, 29.2362)
  line L57 (13.3141, 27.9347) -> (12.8475, 29.2362)
  curve K30 (13.4533, 27.4968) -> (13.3141, 27.9347)
  curve K31 (13.5904, 27.9102) -> (13.4533, 27.4968)
  line L58 (14.0733, 29.2362) -> (13.5904, 27.9102)
  line L59 (14.4519, 29.2362) -> (14.0733, 29.2362)
  line L60 (0, 47.1259) -> (44, 47.1259)
  line L61 (0, 10) -> (0, 47.1259)
  line L62 (44, 10) -> (0, 10)
  line L63 (44, 47.1259) -> (44, 10)
  curve K32
  curve K33
  curve K34
  curve K35
  dimension "d239" Text1-Height = 3
sketch "Sketch4" plane through (40, 0, 0) normal (1, 0, 0) x axis (0, 1, 0)
  line L1 (44.7318, 53.9359) -> (48.9918, 53.9359)
  line L2 (44.7318, 45.6759) -> (44.7318, 53.9359)
  line L3 (48.9918, 45.6759) -> (44.7318, 45.6759)
  line L4 (48.9918, 47.1259) -> (48.9918, 45.6759)
  line L5 (55.6118, 47.1259) -> (48.9918, 47.1259)
  line L6 (55.6118, 52.4859) -> (55.6118, 47.1259)
  line L7 (48.9918, 52.4859) -> (55.6118, 52.4859)
  line L8 (48.9918, 53.9359) -> (48.9918, 52.4859)
  circle C1 centre (44.7318, 49.8059) radius 0.85
  point P10 (44.7318, 49.8059)
  midpoint L2 P10
  dimension "d241" diameter C1 = 1.7 (= "filament_hole_width")
extrude "Extrude4" cut sketch "Sketch4" profile of L2 C1 no distance stored
sketch "Sketch15" plane through (-2, 0, 0) normal (-1, 0, 0) x axis (0, -1, 0)
  line L1 (-19.6118, 60) -> (-19.6118, 23.2332)
  line L2 (-39.6118, 60) -> (-19.6118, 60)
  line L3 (-39.6118, 52.6059) -> (-39.6118, 60)
  line L4 (-33.1118, 52.6059) -> (-39.6118, 52.6059)
  line L5 (-33.1118, 54.0559) -> (-33.1118, 52.6059)
  line L6 (-28.6118, 54.0559) -> (-33.1118, 54.0559)
  line L7 (-28.6118, 45.5559) -> (-28.6118, 54.0559)
  line L8 (-33.1118, 45.5559) -> (-28.6118, 45.5559)
  line L9 (-33.1118, 47.0059) -> (-33.1118, 45.5559)
  line L10 (-39.6118, 47.0059) -> (-33.1118, 47.0059)
  line L11 (-39.6118, 39.6118) -> (-39.6118, 47.0059)
  line L12 (-22.1725, 22.1725) -> (-39.6118, 39.6118)
  arc A1 centre (-21.1118, 23.2332) radius 1.5 clockwise from (-19.6118, 23.2332) to (-22.1725, 22.1725)
  circle C1 centre (-28.6118, 49.8059) radius 0.85
  point P16 (-28.6118, 49.8059)
  midpoint L7 P16
  dimension "d244" diameter C1 = 1.7 (= "filament_hole_width")
extrude "Extrude20" cut sketch "Sketch15" profile of L7 C1 no distance stored
sketch "Sketch9" plane through (44, 0, 0) normal (1, 0, 0) x axis (0, 1, 0)
  line L1 (49.1118, 47.0059) -> (55.6118, 47.0059)
  line L2 (49.1118, 45.5559) -> (49.1118, 47.0059)
  line L3 (44.6118, 45.5559) -> (49.1118, 45.5559)
  line L4 (44.6118, 54.0559) -> (44.6118, 45.5559)
  line L5 (49.1118, 54.0559) -> (44.6118, 54.0559)
  line L6 (49.1118, 52.6059) -> (49.1118, 54.0559)
  line L7 (55.6118, 52.6059) -> (49.1118, 52.6059)
  line L8 (55.6118, 60) -> (55.6118, 52.6059)
  line L9 (39.6118, 60) -> (55.6118, 60)
  line L10 (39.6118, 52.4859) -> (39.6118, 60)
  line L11 (32.9918, 52.4859) -> (39.6118, 52.4859)
  line L12 (32.9918, 53.9359) -> (32.9918, 52.4859)
  line L13 (28.7318, 53.9359) -> (32.9918, 53.9359)
  line L14 (28.7318, 45.6759) -> (28.7318, 53.9359)
  line L15 (32.9918, 45.6759) -> (28.7318, 45.6759)
  line L16 (32.9918, 47.1259) -> (32.9918, 45.6759)
  line L17 (39.6118, 47.1259) -> (32.9918, 47.1259)
  line L18 (39.6118, 10) -> (39.6118, 47.1259)
  line L19 (55.6118, 10) -> (39.6118, 10)
  line L20 (55.6118, 47.0059) -> (55.6118, 10)
  circle C1 centre (28.7318, 49.8059) radius 0.85
  circle C2 centre (44.6118, 49.8059) radius 0.85
  point P22 (28.7318, 49.8059)
  point P23 (44.6118, 49.8059)
  midpoint L14 P22
  midpoint L4 P23
  dimension "d247" diameter C1 = 1.7 (= "filament_hole_width")
  dimension "d250" diameter C2 = 1.7 (= "filament_hole_width")
extrude "Extrude12" cut sketch "Sketch9" profile of L4 L14 C1 C2 no distance stored
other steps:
create_component "CreateComponent1"
create_component "CreateComponent2"
create_component "CreateComponent3"
create_component "CreateComponent4"
named bodies: "Wall anchor part", "Base plate with slot"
